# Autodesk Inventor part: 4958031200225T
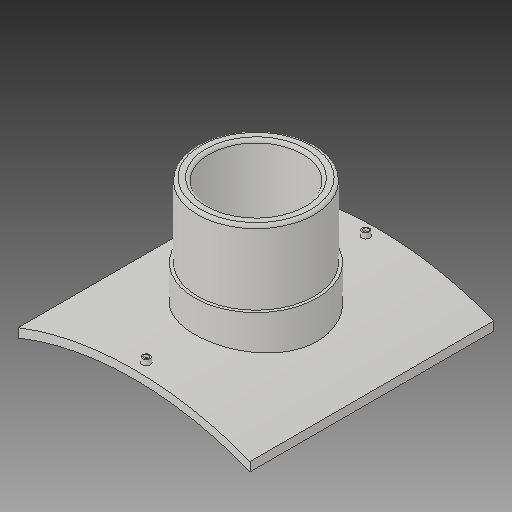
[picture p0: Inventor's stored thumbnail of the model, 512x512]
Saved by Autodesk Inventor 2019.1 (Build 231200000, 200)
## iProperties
Created: 2017-10
Part Number: 4958031200225T
Material: Generic
Description: PLASSON BRANCH SADDLE 1200x225
Document SubType Name: Modeling
Designer: KIM
Mass: 2754.05 g
Surface Area: 3037.44 cm^2
Volume: 2754.05 cm^3
Density: 1 g/cm^3
Appearance: Default
Author: KIM
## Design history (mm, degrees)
derived "495803.ipt"
feature "Solid1::495803.ipt"
tag "TaggingFeature1"
body "Solid1"
other parameters: "d1" = 16, "d2" = 447, "d4" = 0, "d12" = 625.6, "d13" = 14, "d14" = 211.5, "d16" = 5 deg, "d18" = 4, "d19" = 14, "d20" = 0, "d21" = 3, "d22" = 0, "d23" = 819, "d24" = 236.25, "d25" = 16, "d28" = 0, "d29" = 9.6, "d31" = 0, "d32" = 101.5, "d33" = 0, "d34" = 12, "d36" = 225, "d37" = 142.1, "d38" = 0, "d39" = 6, "d_1" = 225, "B_" = 447, "H_" = 203, "x_" = 16, "D_" = 16
